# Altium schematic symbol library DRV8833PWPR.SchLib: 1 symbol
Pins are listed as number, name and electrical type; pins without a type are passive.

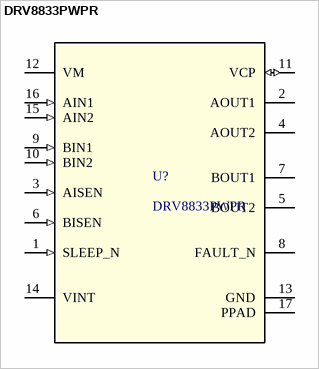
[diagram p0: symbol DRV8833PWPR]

## DRV8833PWPR
designator U?
10.8-V, 2-A dual H-bridge motor driver with current regulation 16-HTSSOP -40 to 85; Manufacturer_Name: Texas Instruments
footprint PWP0016C_N
pins: 1 SLEEP_N (in), 2 AOUT1 (hiz), 3 AISEN (in), 4 AOUT2 (hiz), 5 BOUT2 (hiz), 6 BISEN (in), 7 BOUT1 (hiz), 8 FAULT_N (oc), 9 BIN1 (in), 10 BIN2 (in), 11 VCP (io), 12 VM (power), 13 GND (power), 14 VINT, 15 AIN2 (in), 16 AIN1 (in), 17 PPAD (power)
